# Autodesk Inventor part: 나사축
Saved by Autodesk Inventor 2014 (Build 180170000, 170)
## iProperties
Created: 2026-09
Part Number: 나사축
Material: 일반
Document SubType Name: Modeling
Designer: dg
Density: 1 g/cm^3
Appearance: 기본값
Author: dg
Author: jhkim
Creation Date: 2026-08-27
Sending System: Autodesk Inventor 2027
Preprocessor: ST-DEVELOPER v20.1
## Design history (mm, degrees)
node "나사축1"
node "솔리드1"
node "기준1"
